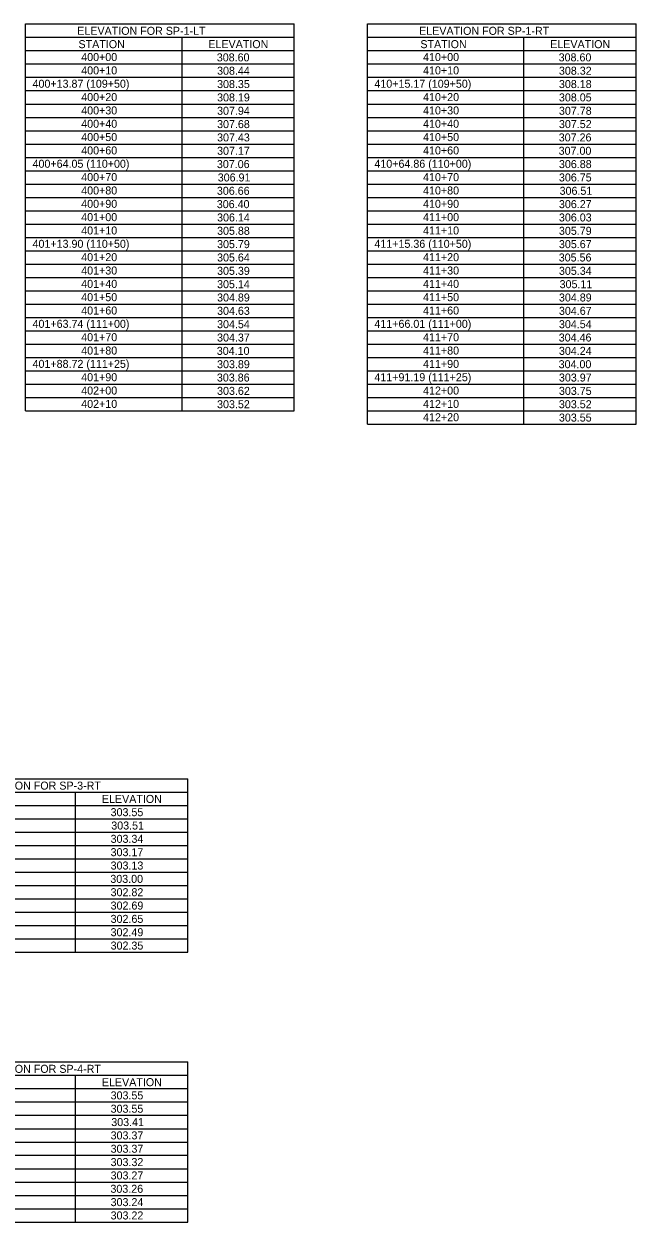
# Model space of a CAD drawing. Extents: x 916322 to 917003, y 328419 to 328887.
# Drawn here: x 916763.4 to 917002.7, y 328419.1 to 328886.8 of the extents above; entities that cross this region are included whole.
import ezdxf

# ---------------------------------------------------------------- set-up
doc = ezdxf.new("R2010")
doc.units = 0
doc.layers.add('ANNOTATION', color=7, linetype='Continuous')

msp = doc.modelspace()

# ---------------------------------------------------------------- linework, layer by layer
at = {"layer": 'ANNOTATION'}
for p, q in [((916764.05, 328886.83), (916869.05, 328886.83)), ((916764.05, 328735.79), (916764.05, 328886.83)), ((916869.05, 328735.79), (916869.05, 328886.83)), ((916897.66, 328886.83), (917002.66, 328886.83)), ((916897.66, 328730.58), (916897.66, 328886.83)), ((917002.66, 328730.58), (917002.66, 328886.83)), ((916764.05, 328881.62), (916869.05, 328881.62)), ((916825.25, 328735.79), (916825.25, 328881.62)), ((916897.66, 328881.62), (917002.66, 328881.62)), ((916958.86, 328730.58), (916958.86, 328881.62)), ((916764.05, 328876.41), (916869.05, 328876.41)), ((916897.66, 328876.41), (917002.66, 328876.41)), ((916764.05, 328871.21), (916869.05, 328871.21)), ((916897.66, 328871.21), (917002.66, 328871.21)), ((916764.05, 328866), (916869.05, 328866)), ((916897.66, 328866), (917002.66, 328866)), ((916764.05, 328860.79), (916869.05, 328860.79)), ((916897.66, 328860.79), (917002.66, 328860.79)), ((916764.05, 328855.58), (916869.05, 328855.58)), ((916897.66, 328855.58), (917002.66, 328855.58)), ((916764.05, 328850.37), (916869.05, 328850.37)), ((916897.66, 328850.37), (917002.66, 328850.37)), ((916764.05, 328845.16), (916869.05, 328845.16)), ((916897.66, 328845.16), (917002.66, 328845.16)), ((916764.05, 328839.96), (916869.05, 328839.96)), ((916897.66, 328839.96), (917002.66, 328839.96)), ((916764.05, 328834.75), (916869.05, 328834.75)), ((916897.66, 328834.75), (917002.66, 328834.75)), ((916764.05, 328829.54), (916869.05, 328829.54)), ((916897.66, 328829.54), (917002.66, 328829.54)), ((916764.05, 328824.33), (916869.05, 328824.33)), ((916897.66, 328824.33), (917002.66, 328824.33)), ((916764.05, 328819.12), (916869.05, 328819.12)), ((916897.66, 328819.12), (917002.66, 328819.12)), ((916764.05, 328813.91), (916869.05, 328813.91)), ((916897.66, 328813.91), (917002.66, 328813.91)), ((916764.05, 328808.71), (916869.05, 328808.71)), ((916897.66, 328808.71), (917002.66, 328808.71)), ((916764.05, 328803.5), (916869.05, 328803.5)), ((916897.66, 328803.5), (917002.66, 328803.5)), ((916764.05, 328798.29), (916869.05, 328798.29)), ((916897.66, 328798.29), (917002.66, 328798.29)), ((916764.05, 328793.08), (916869.05, 328793.08)), ((916897.66, 328793.08), (917002.66, 328793.08)), ((916764.05, 328787.87), (916869.05, 328787.87)), ((916897.66, 328787.87), (917002.66, 328787.87)), ((916764.05, 328782.66), (916869.05, 328782.66)), ((916897.66, 328782.66), (917002.66, 328782.66)), ((916764.05, 328777.46), (916869.05, 328777.46)), ((916897.66, 328777.46), (917002.66, 328777.46)), ((916764.05, 328772.25), (916869.05, 328772.25)), ((916897.66, 328772.25), (917002.66, 328772.25)), ((916764.05, 328767.04), (916869.05, 328767.04)), ((916897.66, 328767.04), (917002.66, 328767.04)), ((916764.05, 328761.83), (916869.05, 328761.83)), ((916897.66, 328761.83), (917002.66, 328761.83)), ((916764.05, 328756.62), (916869.05, 328756.62)), ((916897.66, 328756.62), (917002.66, 328756.62)), ((916764.05, 328751.41), (916869.05, 328751.41)), ((916897.66, 328751.41), (917002.66, 328751.41)), ((916764.05, 328746.21), (916869.05, 328746.21)), ((916897.66, 328746.21), (917002.66, 328746.21)), ((916764.05, 328741), (916869.05, 328741)), ((916897.66, 328741), (917002.66, 328741)), ((916764.05, 328735.79), (916869.05, 328735.79)), ((916897.66, 328735.79), (917002.66, 328735.79)), ((916897.66, 328730.58), (917002.66, 328730.58)), ((916722.44, 328592.14), (916827.44, 328592.14)), ((916827.44, 328524.43), (916827.44, 328592.14)), ((916722.44, 328586.93), (916827.44, 328586.93)), ((916783.64, 328524.43), (916783.64, 328586.93)), ((916722.44, 328581.72), (916827.44, 328581.72)), ((916722.44, 328576.51), (916827.44, 328576.51)), ((916722.44, 328571.3), (916827.44, 328571.3)), ((916722.44, 328566.1), (916827.44, 328566.1)), ((916722.44, 328560.89), (916827.44, 328560.89)), ((916722.44, 328555.68), (916827.44, 328555.68)), ((916722.44, 328550.47), (916827.44, 328550.47)), ((916722.44, 328545.26), (916827.44, 328545.26)), ((916722.44, 328540.05), (916827.44, 328540.05)), ((916722.44, 328534.85), (916827.44, 328534.85)), ((916722.44, 328529.64), (916827.44, 328529.64)), ((916722.44, 328524.43), (916827.44, 328524.43)), ((916722.44, 328481.55), (916827.44, 328481.55)), ((916827.44, 328419.05), (916827.44, 328481.55)), ((916722.44, 328476.35), (916827.44, 328476.35)), ((916783.64, 328419.05), (916783.64, 328476.35)), ((916722.44, 328471.14), (916827.44, 328471.14)), ((916722.44, 328465.93), (916827.44, 328465.93)), ((916722.44, 328460.72), (916827.44, 328460.72)), ((916722.44, 328455.51), (916827.44, 328455.51)), ((916722.44, 328450.3), (916827.44, 328450.3)), ((916722.44, 328445.1), (916827.44, 328445.1)), ((916722.44, 328439.89), (916827.44, 328439.89)), ((916722.44, 328434.68), (916827.44, 328434.68)), ((916722.44, 328429.47), (916827.44, 328429.47)), ((916722.44, 328424.26), (916827.44, 328424.26)), ((916722.44, 328419.05), (916827.44, 328419.05))]:
    msp.add_line(p, q, dxfattribs=at)

# ---------------------------------------------------------------- texts
for s, p in [('ELEVATION FOR SP-1-LT', (916784.26, 328882.59)), ('ELEVATION FOR SP-1-RT', (916917.87, 328882.59)), ('STATION', (916784.75, 328877.38)), ('ELEVATION', (916835.49, 328877.38)), ('STATION', (916918.36, 328877.38)), ('ELEVATION', (916969.1, 328877.38)), ('ELEVATION FOR SP-3-RT', (916742.65, 328587.89)), ('ELEVATION', (916793.88, 328582.69)), ('ELEVATION FOR SP-4-RT', (916742.65, 328477.31)), ('ELEVATION', (916793.88, 328472.1))]:
    msp.add_text(s, height=3.125, rotation=360, dxfattribs=at).set_placement(p)
for s, p in [('400+00', (916785.81, 328872.35)), ('308.60', (916838.8, 328872.22)), ('410+00', (916919.42, 328872.35)), ('308.60', (916972.41, 328872.22)), ('400+10', (916785.81, 328867.14)), ('308.44', (916838.91, 328867.01)), ('410+10', (916919.42, 328867.14)), ('308.32', (916972.52, 328867.01)), ('400+13.87 (109+50)', (916766.79, 328861.93)), ('308.35', (916838.91, 328861.8)), ('410+15.17 (109+50)', (916900.4, 328861.93)), ('308.18', (916972.52, 328861.8)), ('400+20', (916785.81, 328856.72)), ('308.19', (916838.91, 328856.59)), ('410+20', (916919.42, 328856.72)), ('308.05', (916972.52, 328856.59)), ('400+30', (916785.81, 328851.51)), ('307.94', (916838.91, 328851.38)), ('410+30', (916919.42, 328851.51)), ('307.78', (916972.52, 328851.38)), ('400+40', (916785.81, 328846.3)), ('307.68', (916838.91, 328846.17)), ('410+40', (916919.42, 328846.3)), ('307.52', (916972.52, 328846.17)), ('400+50', (916785.81, 328841.1)), ('307.43', (916838.91, 328840.97)), ('410+50', (916919.42, 328841.1)), ('307.26', (916972.45, 328840.97)), ('400+60', (916785.81, 328835.89)), ('307.17', (916838.91, 328835.76)), ('410+60', (916919.42, 328835.89)), ('307.00', (916972.41, 328835.76)), ('400+64.05 (110+00)', (916766.79, 328830.68)), ('307.06', (916838.84, 328830.55)), ('410+64.86 (110+00)', (916900.4, 328830.68)), ('306.88', (916972.52, 328830.55)), ('400+70', (916785.81, 328825.47)), ('306.91', (916839.17, 328825.34)), ('410+70', (916919.42, 328825.47)), ('306.75', (916972.52, 328825.34)), ('400+80', (916785.81, 328820.26)), ('306.66', (916838.84, 328820.13)), ('410+80', (916919.42, 328820.26)), ('306.51', (916972.78, 328820.13)), ('400+90', (916785.81, 328815.05)), ('306.40', (916838.8, 328814.92)), ('410+90', (916919.42, 328815.05)), ('306.27', (916972.52, 328814.92)), ('401+00', (916785.81, 328809.85)), ('306.14', (916838.91, 328809.72)), ('411+00', (916919.42, 328809.85)), ('306.03', (916972.52, 328809.72)), ('401+10', (916785.81, 328804.64)), ('305.88', (916838.91, 328804.51)), ('411+10', (916919.42, 328804.64)), ('305.79', (916972.52, 328804.51)), ('401+13.90 (110+50)', (916766.79, 328799.43)), ('305.79', (916838.91, 328799.3)), ('411+15.36 (110+50)', (916900.4, 328799.43)), ('305.67', (916972.52, 328799.3)), ('401+20', (916785.81, 328794.22)), ('305.64', (916838.91, 328794.09)), ('411+20', (916919.42, 328794.22)), ('305.56', (916972.45, 328794.09)), ('401+30', (916785.81, 328789.01)), ('305.39', (916838.91, 328788.88)), ('411+30', (916919.42, 328789.01)), ('305.34', (916972.52, 328788.88)), ('401+40', (916785.81, 328783.8)), ('305.14', (916838.91, 328783.67)), ('411+40', (916919.42, 328783.8)), ('305.11', (916972.78, 328783.67)), ('401+50', (916785.81, 328778.6)), ('304.89', (916838.91, 328778.47)), ('411+50', (916919.42, 328778.6)), ('304.89', (916972.52, 328778.47)), ('401+60', (916785.81, 328773.39)), ('304.63', (916838.91, 328773.26)), ('411+60', (916919.42, 328773.39)), ('304.67', (916972.52, 328773.26)), ('401+63.74 (111+00)', (916766.79, 328768.18)), ('411+66.01 (111+00)', (916900.4, 328768.18)), ('304.54', (916838.91, 328768.05)), ('304.54', (916972.52, 328768.05)), ('401+70', (916785.81, 328762.97)), ('304.37', (916838.91, 328762.84)), ('411+70', (916919.42, 328762.97)), ('304.46', (916972.45, 328762.84)), ('401+80', (916785.81, 328757.76)), ('304.10', (916838.8, 328757.63)), ('411+80', (916919.42, 328757.76)), ('304.24', (916972.52, 328757.63)), ('401+88.72 (111+25)', (916766.79, 328752.55)), ('303.89', (916838.91, 328752.42)), ('411+90', (916919.42, 328752.55)), ('304.00', (916972.41, 328752.42)), ('401+90', (916785.81, 328747.35)), ('303.86', (916838.84, 328747.22)), ('411+91.19 (111+25)', (916900.4, 328747.35)), ('303.97', (916972.52, 328747.22)), ('402+00', (916785.81, 328742.14)), ('303.62', (916838.91, 328742.01)), ('412+00', (916919.42, 328742.14)), ('303.75', (916972.52, 328742.01)), ('402+10', (916785.81, 328736.93)), ('303.52', (916838.91, 328736.8)), ('412+10', (916919.42, 328736.93)), ('303.52', (916972.52, 328736.8)), ('412+20', (916919.42, 328731.72)), ('303.55', (916972.52, 328731.59)), ('303.55', (916797.3, 328577.52)), ('303.51', (916797.56, 328572.31)), ('303.34', (916797.3, 328567.11)), ('303.17', (916797.3, 328561.9)), ('303.13', (916797.3, 328556.69)), ('303.00', (916797.19, 328551.48)), ('302.82', (916797.3, 328546.27)), ('302.69', (916797.3, 328541.06)), ('302.65', (916797.3, 328535.86)), ('302.49', (916797.3, 328530.65)), ('302.35', (916797.3, 328525.44)), ('303.55', (916797.3, 328466.94)), ('303.55', (916797.3, 328461.73)), ('303.41', (916797.56, 328456.52)), ('303.37', (916797.3, 328451.32)), ('303.37', (916797.3, 328446.11)), ('303.32', (916797.3, 328440.9)), ('303.27', (916797.3, 328435.69)), ('303.26', (916797.23, 328430.48)), ('303.24', (916797.3, 328425.27)), ('303.22', (916797.3, 328420.07))]:
    msp.add_text(s, height=3.125, dxfattribs=at).set_placement(p)

doc.saveas('drawing.dxf')
